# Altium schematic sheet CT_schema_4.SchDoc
size 289 x 230 mm
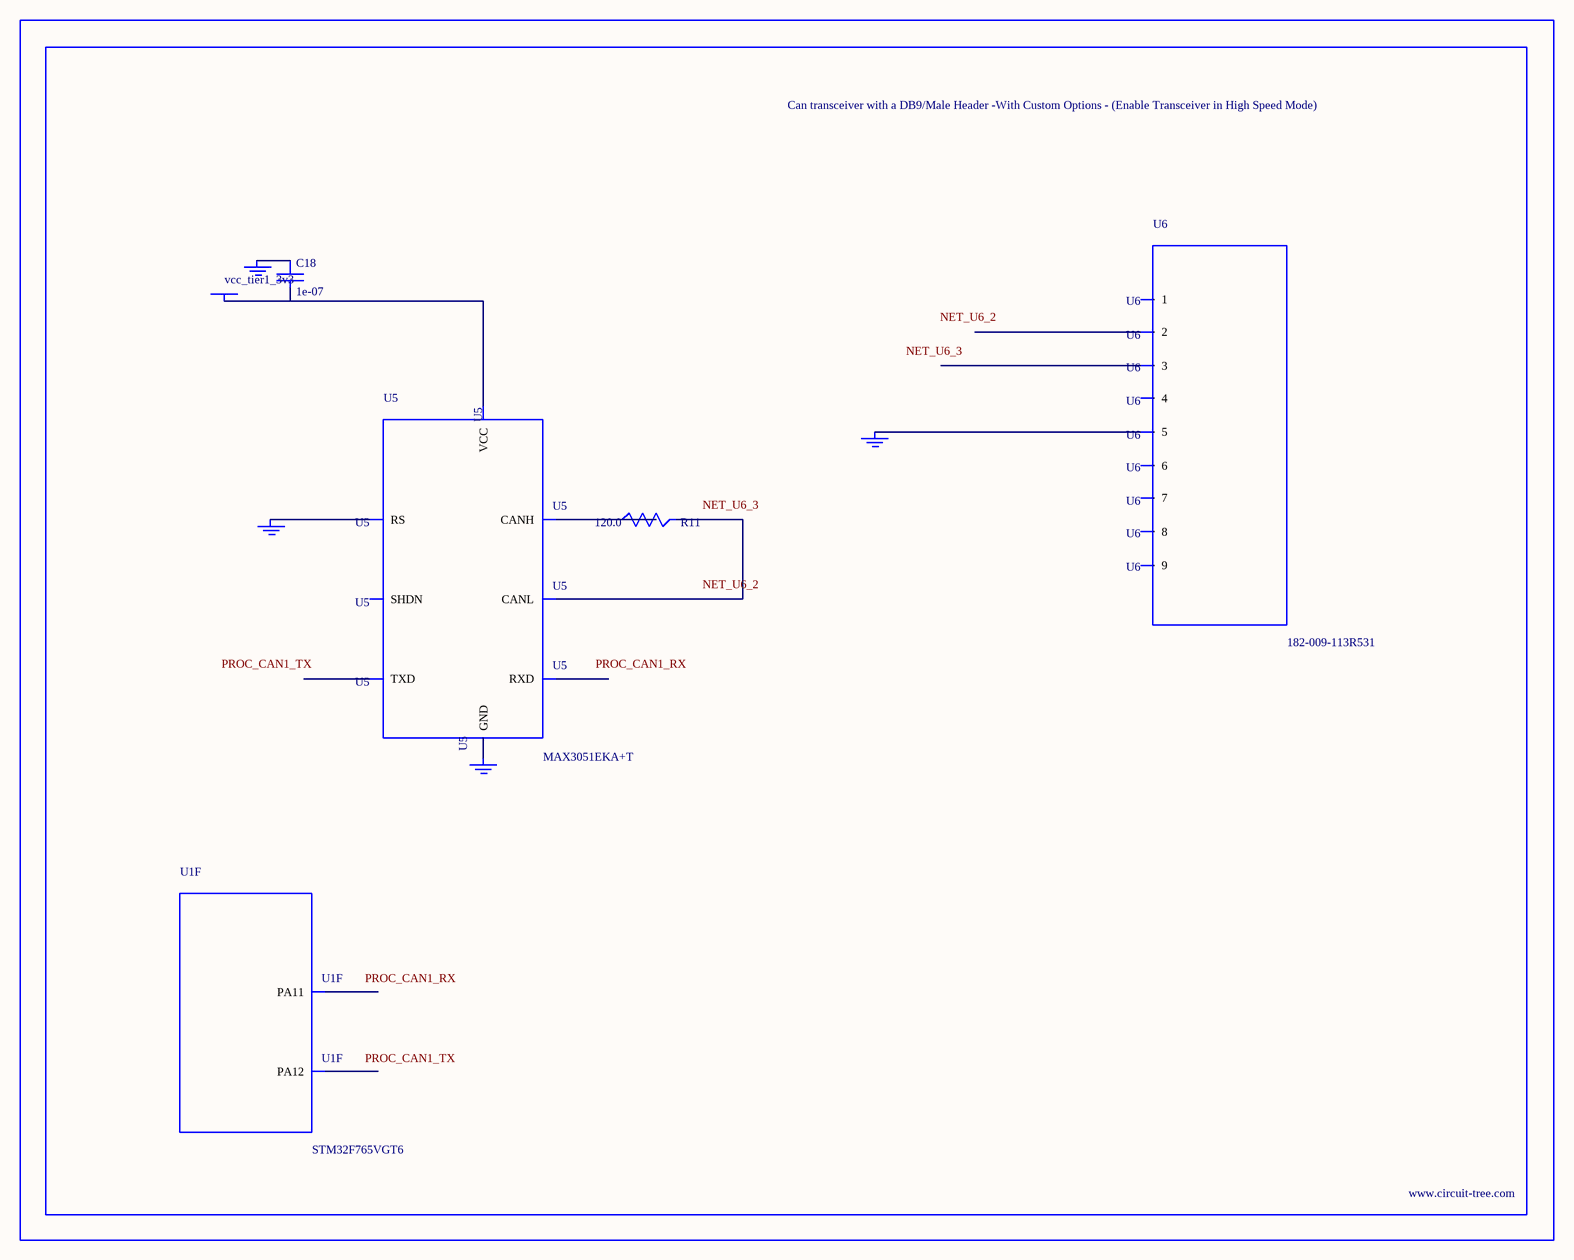
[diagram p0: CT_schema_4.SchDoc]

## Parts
BORDER3  (no value)
C18  1e-07  [C0402]
GND_INSTANCE_3_0  (no value)
GND_INSTANCE_3_1  (no value)
GND_INSTANCE_3_2  (no value)
GND_INSTANCE_3_3  (no value)
POWER_INSTANCE_3_0  vcc_tier1_3v3
R11  120.0  [R0603]
U1  STM32F765VGT6  [LQFP100]  (part F of 8)
U5  MAX3051EKA+T  [SOT-23-8]
U6  182-009-113R531  [182-009-MALE]

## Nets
NetC18_1: C18.1 GND_INSTANCE_3_0.0(GND)
NetC18_2: C18.2 POWER_INSTANCE_3_0.0(PWR) U5.3(VCC)
NetGND_INSTANCE_3_1_0: GND_INSTANCE_3_1.0(GND) U5.8(RS)
NetGND_INSTANCE_3_2_0: GND_INSTANCE_3_2.0(GND) U5.2(GND)
NetGND_INSTANCE_3_3_0: GND_INSTANCE_3_3.0(GND) U6.5
NetR11_1: R11.1 U5.7(CANH)
NetR11_2: R11.2 U5.6(CANL)

Not connected (* = marked no-connect by the designer): U1 70(PA11) 71(PA12); U5 1(TXD) 4(RXD) 5(SHDN); U6 1 2 3 4 6 7 8 9

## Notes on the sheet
- Labels drawn without touching a wire or pin: NET_U6_2, NET_U6_3, PROC_CAN1_RX, PROC_CAN1_TX

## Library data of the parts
BORDER3 = BORDER_PAGE3
C18 = C0402C104K3RACTU
GND_INSTANCE_3_0-GND_INSTANCE_3_3 = GND
POWER_INSTANCE_3_0 = PWR
R11 = RC0603JR-07120RL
